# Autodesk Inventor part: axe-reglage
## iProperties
Shininess: 64.0
Length Units: 11269
Angle Units: 11279
Time Units: 11290
Mass Units: 11283
Length Display Precision: 3
Angle Display Precision: 2
Compacted: True
Part Number: axe-reglage
Document SubType Name: Modeling
Created: 2003-05
Material: Acier doux
Designer: robert
Density: 7.86 g/cm^3
Density: 0.0
Volumn: 0.0
Area: 0.0
PropertySet Name: Model Information
Control State: 0
Master: False
Checked Out: False
Author: robert
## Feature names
1. Extrusion1
2. Extrusion2
3. Extrusion3
4. Extrusion4
5. Extrusion5
6. Perçage1 [Hole]
